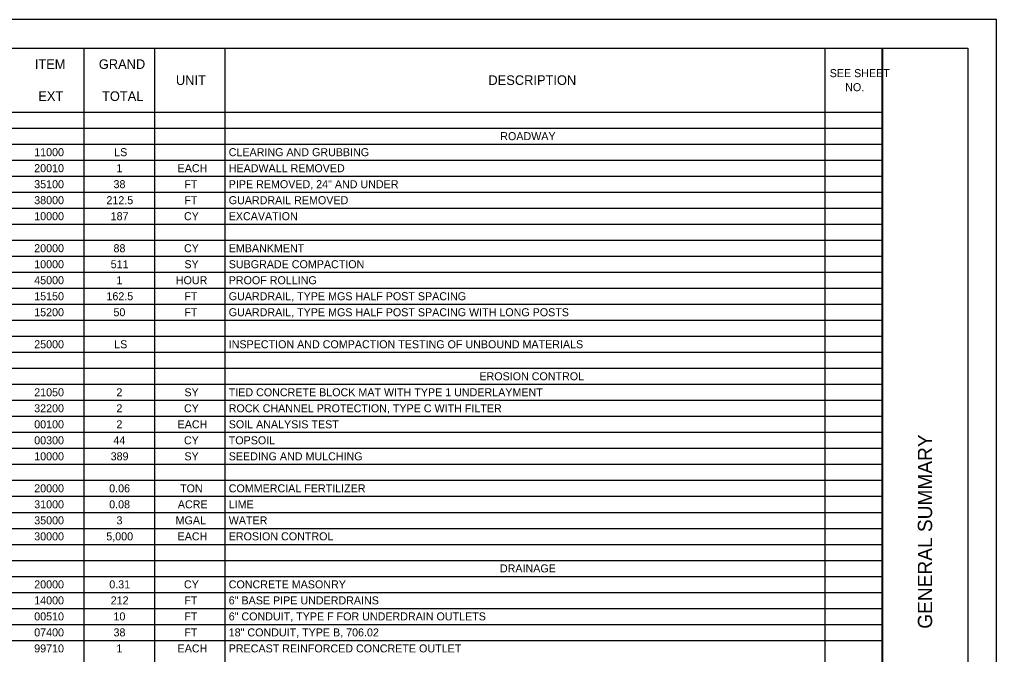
# Model space of a CAD drawing. Extents: x 0 to 34, y 0 to 22.
# Drawn here: x 16.91 to 34, y 10.89 to 22 of the extents above; entities that cross this region are included whole.
import ezdxf

# ---------------------------------------------------------------- set-up
doc = ezdxf.new("R2010")
doc.units = 0
for name, color, linetype in [('SH_Border', 7, 'Continuous'), ('SH_Cut_Line', 7, 'Continuous'), ('SH_Data', 7, 'Continuous'), ('SH_Text', 7, 'Continuous')]:
    doc.layers.add(name, color=color, linetype=linetype)

msp = doc.modelspace()

# ---------------------------------------------------------------- linework, layer by layer
at = {"layer": 'SH_Border'}
msp.add_line((32, 0.5), (32, 21.5), dxfattribs=at)
msp.add_lwpolyline([(1.5, 21.5), (33.5, 21.5), (33.5, 0.5), (1.5, 0.5)], close=True, dxfattribs=at)
at = {"layer": 'SH_Cut_Line'}
msp.add_lwpolyline([(0, 0), (34, 0), (34, 22), (0, 22)], close=True, dxfattribs=at)
at = {"layer": 'SH_Data'}
for p, q in [((1.5, 21.5), (32.004, 21.5)), ((18.036, 21.5), (18.036, 0.5)), ((19.272, 21.5), (19.272, 0.5)), ((20.507, 21.5), (20.507, 0.5)), ((30.999, 21.5), (30.999, 0.5)), ((32.004, 21.5), (32.004, 0.5)), ((1.5, 20.38), (32.004, 20.38)), ((1.5, 20.1), (32.004, 20.1)), ((1.5, 19.82), (32.004, 19.82)), ((1.5, 19.54), (32.004, 19.54)), ((1.5, 19.26), (32.004, 19.26)), ((1.5, 18.98), (32.004, 18.98)), ((1.5, 18.7), (32.004, 18.7)), ((1.5, 18.42), (32.004, 18.42)), ((1.5, 18.14), (32.004, 18.14)), ((1.5, 17.86), (32.004, 17.86)), ((1.5, 17.58), (32.004, 17.58)), ((1.5, 17.3), (32.004, 17.3)), ((1.5, 17.02), (32.004, 17.02)), ((1.5, 16.74), (32.004, 16.74)), ((1.5, 16.46), (32.004, 16.46)), ((1.5, 16.18), (32.004, 16.18)), ((1.5, 15.9), (32.004, 15.9)), ((1.5, 15.62), (32.004, 15.62)), ((1.5, 15.34), (32.004, 15.34)), ((1.5, 15.06), (32.004, 15.06)), ((1.5, 14.78), (32.004, 14.78)), ((1.5, 14.5), (32.004, 14.5)), ((1.5, 14.22), (32.004, 14.22)), ((1.5, 13.94), (32.004, 13.94)), ((1.5, 13.66), (32.004, 13.66)), ((1.5, 13.38), (32.004, 13.38)), ((1.5, 13.1), (32.004, 13.1)), ((1.5, 12.82), (32.004, 12.82)), ((1.5, 12.54), (32.004, 12.54)), ((1.5, 12.26), (32.004, 12.26)), ((1.5, 11.98), (32.004, 11.98)), ((1.5, 11.7), (32.004, 11.7)), ((1.5, 11.42), (32.004, 11.42)), ((1.5, 11.14), (32.004, 11.14))]:
    msp.add_line(p, q, dxfattribs=at)

# ---------------------------------------------------------------- texts
msp.add_text('GENERAL SUMMARY', height=0.25, rotation=90, dxfattribs=at).set_placement((32.875, 11.344))
at = {"layer": 'SH_Text'}
for s, height, p in [('ITEM', 0.168, (17.181, 21.136)), ('GRAND', 0.168, (18.301, 21.136)), ('UNIT', 0.168, (19.649, 20.856)), ('DESCRIPTION', 0.168, (25.115, 20.856)), ('SEE SHEET ', 0.14, (31.084, 20.992)), ('NO.', 0.14, (31.354, 20.747)), ('EXT', 0.168, (17.242, 20.576)), ('TOTAL', 0.168, (18.357, 20.576)), ('ROADWAY', 0.14, (25.322, 19.89)), ('11000', 0.14, (17.171, 19.61)), ('LS', 0.14, (18.57, 19.61)), ('CLEARING AND GRUBBING', 0.14, (20.573, 19.61)), ('20010', 0.14, (17.171, 19.33)), ('1', 0.14, (18.609, 19.33)), ('EACH', 0.14, (19.679, 19.33)), ('HEADWALL REMOVED', 0.14, (20.573, 19.33)), ('35100', 0.14, (17.171, 19.05)), ('38', 0.14, (18.558, 19.05)), ('FT', 0.14, (19.796, 19.05)), ('PIPE REMOVED, 24" AND UNDER', 0.14, (20.573, 19.05)), ('38000', 0.14, (17.171, 18.77)), ('212.5', 0.14, (18.434, 18.77)), ('FT', 0.14, (19.796, 18.77)), ('GUARDRAIL REMOVED', 0.14, (20.573, 18.77)), ('10000', 0.14, (17.171, 18.49)), ('187', 0.14, (18.508, 18.49)), ('CY', 0.14, (19.79, 18.49)), ('EXCAVATION', 0.14, (20.573, 18.49)), ('20000', 0.14, (17.171, 17.93)), ('88', 0.14, (18.558, 17.93)), ('CY', 0.14, (19.79, 17.93)), ('EMBANKMENT', 0.14, (20.573, 17.93)), ('10000', 0.14, (17.171, 17.65)), ('511', 0.14, (18.509, 17.65)), ('SY', 0.14, (19.798, 17.65)), ('SUBGRADE COMPACTION', 0.14, (20.573, 17.65)), ('45000', 0.14, (17.171, 17.37)), ('1', 0.14, (18.609, 17.37)), ('HOUR', 0.14, (19.648, 17.37)), ('PROOF ROLLING', 0.14, (20.573, 17.37)), ('15150', 0.14, (17.171, 17.09)), ('162.5', 0.14, (18.434, 17.09)), ('FT', 0.14, (19.796, 17.09)), ('GUARDRAIL, TYPE MGS HALF POST SPACING', 0.14, (20.573, 17.09)), ('15200', 0.14, (17.171, 16.81)), ('50', 0.14, (18.557, 16.81)), ('FT', 0.14, (19.796, 16.81)), ('GUARDRAIL, TYPE MGS HALF POST SPACING WITH LONG POSTS', 0.14, (20.573, 16.81)), ('25000', 0.14, (17.171, 16.25)), ('LS', 0.14, (18.57, 16.25)), ('INSPECTION AND COMPACTION TESTING OF UNBOUND MATERIALS', 0.14, (20.573, 16.25)), ('EROSION CONTROL', 0.14, (24.957, 15.69)), ('21050', 0.14, (17.171, 15.41)), ('2', 0.14, (18.609, 15.41)), ('SY', 0.14, (19.798, 15.41)), ('TIED CONCRETE BLOCK MAT WITH TYPE 1 UNDERLAYMENT', 0.14, (20.573, 15.41)), ('32200', 0.14, (17.171, 15.13)), ('2', 0.14, (18.609, 15.13)), ('CY', 0.14, (19.79, 15.13)), ('ROCK CHANNEL PROTECTION, TYPE C WITH FILTER', 0.14, (20.573, 15.13)), ('00100', 0.14, (17.171, 14.85)), ('2', 0.14, (18.609, 14.85)), ('EACH', 0.14, (19.679, 14.85)), ('SOIL ANALYSIS TEST', 0.14, (20.573, 14.85)), ('00300', 0.14, (17.171, 14.57)), ('44', 0.14, (18.556, 14.57)), ('CY', 0.14, (19.79, 14.57)), ('TOPSOIL', 0.14, (20.573, 14.57)), ('10000', 0.14, (17.171, 14.29)), ('389', 0.14, (18.508, 14.29)), ('SY', 0.14, (19.798, 14.29)), ('SEEDING AND MULCHING', 0.14, (20.573, 14.29)), ('20000', 0.14, (17.171, 13.73)), ('0.06', 0.14, (18.482, 13.73)), ('TON', 0.14, (19.722, 13.73)), ('COMMERCIAL FERTILIZER', 0.14, (20.573, 13.73)), ('31000', 0.14, (17.171, 13.45)), ('0.08', 0.14, (18.482, 13.45)), ('ACRE', 0.14, (19.683, 13.45)), ('LIME', 0.14, (20.573, 13.45)), ('35000', 0.14, (17.171, 13.17)), ('3', 0.14, (18.61, 13.17)), ('MGAL', 0.14, (19.644, 13.17)), ('WATER', 0.14, (20.573, 13.17)), ('30000', 0.14, (17.171, 12.89)), ('5,000', 0.14, (18.432, 12.89)), ('EACH', 0.14, (19.679, 12.89)), ('EROSION CONTROL', 0.14, (20.573, 12.89)), ('DRAINAGE', 0.14, (25.316, 12.33)), ('20000', 0.14, (17.171, 12.05)), ('0.31', 0.14, (18.484, 12.05)), ('CY', 0.14, (19.79, 12.05)), ('CONCRETE MASONRY', 0.14, (20.573, 12.05)), ('14000', 0.14, (17.171, 11.77)), ('212', 0.14, (18.509, 11.77)), ('FT', 0.14, (19.796, 11.77)), ('6" BASE PIPE UNDERDRAINS', 0.14, (20.573, 11.77)), ('00510', 0.14, (17.171, 11.49)), ('10', 0.14, (18.557, 11.49)), ('FT', 0.14, (19.796, 11.49)), ('6" CONDUIT, TYPE F FOR UNDERDRAIN OUTLETS', 0.14, (20.573, 11.49)), ('07400', 0.14, (17.171, 11.21)), ('38', 0.14, (18.558, 11.21)), ('FT', 0.14, (19.796, 11.21)), ('18" CONDUIT, TYPE B, 706.02', 0.14, (20.573, 11.21)), ('99710', 0.14, (17.171, 10.93)), ('1', 0.14, (18.609, 10.93)), ('EACH', 0.14, (19.679, 10.93)), ('PRECAST REINFORCED CONCRETE OUTLET', 0.14, (20.573, 10.93))]:
    msp.add_text(s, height=height, dxfattribs=at).set_placement(p)

doc.saveas('drawing.dxf')
